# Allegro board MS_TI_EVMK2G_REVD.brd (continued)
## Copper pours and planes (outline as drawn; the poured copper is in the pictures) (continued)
VCC3V3_CP2105 on TOP: 15.57,60.06 15.57,56.23 15.63,56.16 15.63,54.74 16.76,53.61 21.34,53.61 21.46,53.74 21.46,56.02 21.21,56.28 20.07,56.28 19.69,55.89 19.69,55.26 19.43,55.01 17.91,55.01 17.78,55.13 17.78,58.05 18.29,58.56 18.29,60.34 18.16,60.47 16.59,60.47 16.28,60.16 15.67,60.16
VCC3V3_DC_CONN on TOP: 26.04,186.15 26.04,185 26.72,184.32 36.45,184.32 37.24,185.1 37.24,188.08 36.65,188.66 33.58,188.66 31.39,186.48 26.37,186.48
VCC3V3_DC_CONN on TOP: 239.9,238.27 239.9,237.89 247.01,237.89 247.43,238.31 247.43,239.63 247.78,239.97 247.78,243.6 247.27,244.11 243.59,244.11 243.2,243.73 243.2,241.31 242.95,241.06 240.16,241.06 240.03,240.93 240.03,238.39
VCC3V3_DC_CONN on TOP: 200.25,232.91 200.56,232.6 200.56,231.87 200.91,231.51 202.23,231.51 202.39,231.66 202.39,234.36 202.08,234.66 201.63,234.66 201.5,234.79 201.5,235.78 201.17,236.11 199.52,236.11 199.26,235.85 199.26,233.19 199.54,232.91
VCC3V3_DC_CONN on TOP: 26.67,150.51 26.67,148.6 27.31,147.97 30.48,147.97 31.12,148.6 31.12,149.24 31.75,149.87 33.66,149.87 34.29,150.51 34.29,151.14 33.66,151.78 31.12,151.78 29.85,150.51
VCC3V3_DC_CONN on TOP: 224.16,220.87 224.41,220.61 233.3,220.61 234.06,221.38 234.06,230.77 233.43,231.41 229.97,231.41 229.59,231.79 229.59,235.85 229.62,235.88 229.62,237.5 230.38,238.27 233.81,238.27 234.06,238.52 234.06,239.79 233.55,240.3 224.66,240.3 224.16,239.79
VCC3V3_DC_CONN on TOP: 200.28,227.14 200.28,226.02 200.69,225.62 203.86,225.62 204.37,226.13 204.37,227.17 204.17,227.37 200.51,227.37
VCC3V3_DC_CONN on BOTTOM: 225.68,220.82 226.67,219.83 235.2,219.83 236.14,220.77 236.14,225.08 234.52,226.71 230.68,226.71 229.84,227.55 229.84,228.84 229.87,228.87 229.87,237.89 229.36,238.39 226.19,238.39 225.68,237.89
VCC3V3_DC_CONN on L05_PWR1: 4.7,147.08 2.01,149.77 2.01,236.13 14.1,248.22 14.1,249.95 14.5,250.36 230.28,250.36 249.35,250.43 249.94,249.95 249.94,231.03 249.3,230.39 238.38,230.39 236.98,229 236.98,223.92 234.7,221.63 201.14,221.63 199.26,223.51 199.26,231.92 198.75,231.92 198.12,232.55 198.12,233.06 198.25,233.19 198.32,233.19 197.17,234.34 100.7,234.34 95.22,228.87 38.1,228.87 34.29,225.06 34.21,225.06 32.38,223.23 32.36,223.23 32.36,192.12 35.94,188.53 35.94,149.87 33.15,147.08 ; 1 cut-out
VCC3V3_DCIN on TOP: 106.05,187.21 106.05,181.75 105.16,180.86 105.16,179.47 105.28,179.34 108.71,179.34 109.09,179.72 109.09,187.09 108.59,187.59 106.43,187.59
VCC3V3_DCIN on TOP: 107.59,25.01 107.59,23.59 107.16,23.15 105.28,23.15 105.03,23.41 105.03,24.88 105.28,25.14 107.47,25.14
VCC3V3_DCIN on TOP: 231.01,174 243.38,174 243.89,173.5 244.6,173.5 244.73,173.62 244.73,173.88 244.6,174 243.89,174 243.38,174.51 243.2,174.64 240.79,174.64 239.9,175.53 231.01,175.53
VCC3V3_DCIN on TOP: 286.66,199.81 288.98,199.81 290.75,201.59 290.75,202.86 286.69,202.86 286.66,202.83
VCC3V3_DCIN on TOP: 244.09,173.37 244.09,172.99 240.66,172.99 239.39,171.72 230.89,171.72 230.89,173.37
VCC3V3_DCIN on TOP: 278.1,183.73 278.1,192.09 277.11,193.08 277.11,201.64 271.53,201.64 271.53,183.73
VCC3V3_DCIN on TOP: 146.18,105.81 146.18,103.39 145.8,103.01 145.8,98.95 146.05,98.69 148.08,98.69 148.21,98.82 148.21,101.23 148.72,101.74 149.86,101.74 150.24,101.36 150.24,99.2 149.99,98.95 149.99,96.03 150.11,95.9 152.27,95.9 152.4,96.03 152.4,104.41 150.88,105.93 146.3,105.93
VCC3V3_DCIN on TOP: 114.55,194.58 114.94,194.2 118.36,194.2 118.49,194.32 118.49,197.63 117.98,198.13 117.98,200.67 117.86,200.8 116.08,200.8 115.95,200.67 115.95,198.01 116.33,197.63 116.33,196.61 116.08,196.36 114.68,196.36 114.55,196.23
VCC3V3_DCIN on TOP: 86.08,178.73 86.08,176.88 86.13,176.82 94.67,176.82 95.53,175.96 95.53,171.69 95.76,171.46 98.78,171.46 99.36,172.05 99.36,177.31 97.92,178.75 94.82,178.75 94.77,178.7 86.11,178.7
VCC3V3_DCIN on TOP: 274.07,160.42 274.07,152.92 274.7,152.29 286.26,152.29 287.27,153.3 287.27,161.3 286.26,162.32 275.97,162.32
VCC3V3_DCIN on TOP: 148.97,47.94 148.97,46.19 149.33,45.84 153.62,45.84 153.95,46.17 153.95,47.36 153.26,48.05 149.12,48.05 149.02,47.94
VCC3V3_DCIN on BOTTOM: 250.16,176.62 250.16,174.18 252.78,174.18 252.78,176.62
VCC3V3_DCIN on BOTTOM: 274.19,158.51 274.19,153.81 273.81,153.43 273.81,150.76 274.07,150.51 274.07,148.99 274.45,148.6 276.48,148.6 276.86,148.99 276.86,151.78 277.11,152.03 280.92,152.03 281.31,152.41 281.31,158.76 281.05,159.02 274.7,159.02
VCC3V3_DCIN on BOTTOM: 230.76,177.18 230.76,170.07 231.52,169.31 243.97,169.31 244.22,169.56 244.22,170.32 243.71,170.83 242.19,170.83 241.43,171.59 241.43,175.15 238.38,178.2 231.77,178.2
VCC3V3_DCIN on BOTTOM: 115.47,200.04 115.47,191.68 118.31,188.84 118.31,183.99 116.15,181.83 116.15,178.58 116.76,177.97 119.56,177.97 120.22,178.63 120.22,190.59 118.34,192.47 118.29,192.47 118.29,194.22 119.05,194.99 119.05,197.32 118.06,198.31 118.06,199.51 117.45,200.12 115.54,200.12
VCC3V3_DCIN on BOTTOM: 149.15,47.51 149.15,45.94 149.56,45.53 153.97,45.53 154.43,45.99 154.43,47.46 154.08,47.82 151.51,47.82 151.28,47.59 149.22,47.59
VCC3V3_DCIN on L03_SIG1: 164.08,142 164.08,140.98 163.7,140.6 161.16,140.6 160.74,141.02 160.74,141.76 160.66,141.85 160.66,142.81 160.05,143.42 160.05,146.98 161.67,148.6 164.59,148.6 164.72,148.48 164.72,147.33 165.1,146.95 165.35,146.95 165.61,147.21 165.61,148.1 166.24,148.73 169.04,148.73 170.18,147.59 170.18,146.7 169.93,146.45 169.16,146.45 169.04,146.57 169.04,147.08 168.15,147.97 166.62,147.97 166.37,147.72 166.37,147.33 166.75,146.95 166.88,146.95 167.51,146.32 167.51,144.67 166.75,143.91 162.18,143.91 161.8,143.52 161.8,142.51 162.05,142.25 163.83,142.25
VCC3V3_DCIN on L03_SIG1: 105.66,23.61 105.66,24.68 107.06,24.68 107.06,23.61
VCC3V3_DCIN on L05_PWR1: outline of 88 points within 4.83,8.14 291.46,233.19
VCC3V3_DCIN on L06_PWR2: outline of 120 points within 118.11,8.27 298.45,206.64 ; 1 cut-out
VCC3V3_HDMI on TOP: 113.54,31.76 113.54,25.92 112.78,25.16 108.48,25.16 108.23,25.41 106.38,25.41 106.17,25.62 106.17,28.39 106.38,28.59 108.41,28.59 108.84,29.02 108.84,31.76
VCC3V3_MLB on L06_PWR2: 119.08,22.01 119.08,16.02 118.11,15.05 118.11,8.9 118.75,8.27 131.95,8.27 132.41,8.73 132.41,35.07 131.22,36.26 127.28,36.26 126.75,35.73 126.75,29.63 119.13,22.01
VCC3V3_NAND on TOP: 116.71,131.71 116.71,127.78 116.97,127.52 121.79,127.52 122.17,127.9 122.17,131.21 121.54,131.84 116.84,131.84
VCC3V3_NAND on TOP: 114.81,111.77 114.81,109.49 115.19,109.11 117.86,109.11 118.11,108.85 118.11,107.2 117.98,107.08 117.98,105.81 118.75,105.04 123.95,105.04 124.33,105.42 124.46,105.42 124.46,111.01 123.06,112.41 115.44,112.41
VCC3V3_PCIE on TOP: 202.77,234.66 202.77,232.7 202.9,232.58 203.91,232.58 204.04,232.7 206.78,232.7 206.91,232.58 210.19,232.58 210.26,232.65 210.26,233.34 210.13,233.47 207.75,233.47 207.34,233.87 204.39,233.87 203.78,234.48 203.78,237.05 203.25,237.58 202.29,237.58 201.88,237.17 201.88,235.09 202.08,234.89 202.54,234.89
VCC3V3_PCIE on TOP: 214.88,232.42 214.88,230.52 217.42,230.52 217.68,230.27 217.68,226.33 217.93,226.07 223.01,226.07 223.65,226.71 223.65,239.41 223.27,239.79 221.36,239.79 221.11,239.54 221.11,234.96 220.98,234.84 218.82,234.84 218.19,234.2 218.19,232.81 217.8,232.42
VCC3V3_PCIE on BOTTOM: 202.18,226.84 202.82,226.2 224.16,226.2 224.66,226.71 224.66,238.14 224.61,238.19 224.69,238.27 224.69,244.49 225.2,245 228.22,245 228.47,245.25 228.47,250.13 228.32,250.28 206.2,250.28 206.17,250.31 202.54,250.31 202.18,249.95
VCC3V3_PCIE on L03_SIG1: 217.55,231.28 217.55,226.33 218.06,225.82 223.52,225.82 224.66,226.96 224.66,236.11 225.42,236.87 230.25,236.87 230.89,237.5 230.89,248.43 230.12,249.19 225.3,249.19 224.54,248.43 224.54,245.38 226.06,243.85 226.06,240.68 225.55,240.17 221.61,240.17 221.23,239.79 221.23,234.96
VCC3V3_PCIE_AUX on TOP: 200.81,228.08 201.02,227.88 203.07,227.88 203.33,228.13 206.22,228.13 207.47,229.38 207.47,230.19 207.85,230.57 210.13,230.57 210.31,230.75 210.31,231.28 210.16,231.43 207.44,231.43 207.21,231.21 206.12,231.21 205.92,231 205.92,229.81 205.82,229.71 203.71,229.71 203.56,229.86 203.56,230.75 203.23,231.08 200.99,231.08 200.81,230.9
VCC3V3_QSPI on BOTTOM: 188.09,79.14 188.09,76.98 188.59,76.47 192.15,76.47 193.04,75.58 193.04,73.8 193.29,73.55 194.69,73.55 195.71,72.53 195.71,69.23 196.72,68.21 202.69,68.21 203.58,69.1 203.58,69.86 203.07,70.37 202.56,70.37 202.44,70.5 202.44,73.17 203.33,74.06 204.85,74.06 205.36,74.56 205.36,77.61 204.72,78.25 202.82,78.25 202.69,78.12 202.69,76.34 201.8,75.45 197.1,75.45 196.34,76.21 196.34,81.04 196.22,81.17 194.56,81.17 194.31,80.91 194.31,79.77 194.06,79.52 188.47,79.52
VCC3V3_SER_EXP on TOP: 294.54,243.75 294.54,239.26 294.69,239.11 296.21,239.11 296.6,239.49 301.04,239.49 301.62,238.9 301.62,233.69 302.06,233.26 304.06,233.26 304.47,233.67 304.47,241.31 304.09,241.7 297.89,241.7 297.31,242.28 297.31,243.09 296.32,244.08 294.87,244.08
VCC3V3_XDS on TOP: 226.82,50.81 222.88,50.81 222.25,50.18 222.25,39.77 222.88,39.13 226.31,39.13 226.82,39.64
VCC3V3_XDS on L06_PWR2: 225.81,103.65 245.24,103.65 248.41,106.82 297.18,106.82 297.81,106.19 297.81,13.22 293.75,9.16 188.47,9.16 187.71,9.92 187.71,68.72 188.98,69.99 188.98,76.72 191.64,79.39 234.82,79.39 239.65,84.22 239.65,96.15 235.97,99.84 227.2,99.84 225.81,101.23
VCC3V3_XDS_DVDD33 on TOP: 227.2,41.16 227.2,38.62 227.33,38.5 229.36,38.5 229.62,38.75 229.62,40.91 229.23,41.29 227.33,41.29
VCC3V3_XDS_DVDD33 on L06_PWR2: 227.46,59.07 247.4,59.07 247.4,50.43 247.78,50.05 253.87,50.05 255.14,48.78 255.14,43.45 254.25,42.56 244.47,42.56 242.63,40.72 237.93,40.72 236.73,39.51 230.5,39.51 229.74,38.75 227.46,38.75 227.08,39.13 227.08,58.69
VCC5V0_DCDC on TOP: 246.13,176.16 246,176.29 246,176.54 245.62,176.93 245.62,178.83 245.75,178.96 245.75,179.47 246,179.72 247.27,179.72 247.78,180.23 247.78,181.12 247.27,181.62 247.27,185.31 247.65,185.69 251.97,185.69 252.35,185.31 252.35,181.37 251.71,180.74 251.08,180.74 250.82,180.48 250.82,179.59 250.7,179.47 250.19,179.47 249.3,178.58 247.01,178.58 246.25,177.81 246.25,176.93 246.63,176.54 246.63,176.29 246.51,176.16
VCC5V0_DCDC on TOP: 245.62,205.75 252.22,205.75 252.48,206.01 252.48,214.14 253.75,215.41 253.75,224.55 252.73,225.57 247.14,225.57 245.36,223.79 245.36,206.01
VCC5V0_DCDC on TOP: 283.95,94.86 283.18,95.62 282.17,95.62 282.17,95.11 282.55,94.73 282.55,93.49 283.21,92.83 285.47,92.83 285.47,94.35 284.2,94.35 283.95,94.6
VCC5V0_DCDC on TOP: 242.06,161.05 243.59,161.05 243.84,161.3 243.84,163.72 243.33,164.23 243.33,165.5 243.59,165.75 244.35,165.75 244.6,166 244.6,167.53 244.73,167.65 244.73,169.31 244.6,169.43 244.47,169.43 244.35,169.31 244.35,168.29 243.33,167.27 243.33,166.77 242.82,166.26 242.82,164.61 241.81,163.59 241.81,161.3
VCC5V0_DCDC on TOP: 189.61,232.04 190.12,231.54 192.66,231.54 192.91,231.79 192.91,233.82 192.53,234.2 189.74,234.2 189.61,234.08
VCC5V0_DCDC on TOP: 252.48,160.8 252.48,164.23 251.78,164.92 251.78,169.24 251.46,169.56 249.05,169.56 247.9,170.7 246.89,170.7 246.76,170.58 246.76,170.32 246.89,170.19 247.78,170.19 248.41,169.56 248.41,169.31 248.92,168.8 250.06,168.8 250.57,168.29 250.57,167.02 249.81,166.26 249.81,160.8 250.06,160.54 252.22,160.54
VCC5V0_DCDC on TOP: 285.47,99.18 283.95,99.18 282.42,97.65 282.42,96.89 283.18,96.89 283.69,97.4 285.47,97.4
VCC5V0_DCDC on TOP: 280.14,100.95 279.12,100.95 278.87,100.7 278.87,99.18 279.02,99.02 279.98,99.02 280.14,99.18
VCC5V0_DCDC on BOTTOM: 252.83,172.99 252.83,172.35 257.43,172.35 257.43,173.88 253.72,173.88
VCC5V0_DCDC on BOTTOM: 242.49,163.57 242.49,161.79 243.87,161.79 244.55,161.1 244.55,159.55 246.43,159.55 246.43,163.57
VCC5V0_DCDC on L05_PWR1: outline of 90 points within 179.07,8.4 304.16,249.32 ; 4 cut-outs
VCC5V0_LCD on BOTTOM: 32.13,84.77 32.13,86.63 33.02,87.52 47.27,87.52 48.23,86.55 48.23,68.06 46.2,66.03 32.89,66.03 32.26,66.66 32.26,84.65
VCC5V0_USB0_PM on TOP: 217.27,32.35 219.79,32.35 219.79,34.18 219.48,34.48 217.63,34.48 217.27,34.13
VCC5V0_USB0_PM on TOP: 222.28,52.19 222.28,55.54 217.86,55.54 217.86,52.19
VCC5V0_USB0_PM on BOTTOM: 222.63,55.01 221.87,55.77 220.6,55.77 219.89,55.06 219.89,42.18 217.3,39.59 217.3,32.55 217.93,31.92 221.89,31.92 222.63,32.65
VCC5V0_USB1_PM on TOP: 191.47,22.93 191.47,21.05 191.8,20.72 195.48,20.72 196.06,21.3 196.06,22.72 195.68,23.1 191.64,23.1
VCC5V0_USB1_PM on BOTTOM: 199.24,28.97 199.24,25.16 199.64,24.75 200.36,24.75 200.66,24.45 200.66,23.51 200.41,23.26 191.13,23.26 190.75,22.87 190.75,20.41 191.19,19.98 203.15,19.98 203.83,20.67 203.83,28.84 203.48,29.2 199.47,29.2
VCC5V_VUSB_CP2105 on L08_SIG2: 13.13,62.8 13.13,56.76 13.41,56.48 19.08,56.48 19.56,56.96 19.56,57.72 17.96,59.32 17.96,62.91 17.17,63.69 14.02,63.69
VCC12V0_AUD_EXP on TOP: 293.88,160.92 293.88,158.13 293.75,158 293.75,155.84 293.37,155.46 293.37,152.41 293.5,152.29 294,152.29 294.13,152.16 294.13,149.37 294.77,148.73 297.18,148.73 298.32,147.59 298.32,137.68 298.7,137.3 304.5,137.3 304.56,137.37 304.56,147.58 303.91,148.22 299.59,148.22 297.69,150.13 297.69,160.8 296.8,161.69 294.64,161.69
VCC12V0_AUD_EXP on BOTTOM, L03_SIG1, L08_SIG2: 294.13,157.88 294.13,137.68 294.64,137.17 304.04,137.17 304.55,137.68 304.55,146.19 302.89,147.84 299.97,147.84 297.56,150.26 297.56,158.76 296.67,159.65 294.39,159.65 294,159.27 294,158
VCC12V0_DC_IN on TOP: 133.6,226.58 132.59,226.58 132.59,223.53 132.33,223.28 132.33,217.69 131.57,216.93 131.57,213.12 132.59,212.1 136.65,212.1 137.16,212.61 137.16,219.72 133.6,223.28
VCC12V0_DC_IN on TOP: 291.85,156.22 291.97,156.1 293.24,156.1 293.37,156.22 293.37,161.1 294.11,161.84 294.11,163.18 292.07,163.18 291.85,162.96
VCC12V0_DC_IN on TOP: 239.9,237.58 239.9,235.73 240.16,235.47 240.28,235.47 240.79,234.96 240.79,226.2 240.92,226.07 243.33,226.07 243.46,226.2 243.46,237.53 243.41,237.58
VCC12V0_DC_IN on TOP: 245.54,188.23 239.27,188.23 238.76,187.72 230.5,187.72 230.25,187.97 230.25,190.01 230.38,190.13 242.32,190.13 242.7,189.75 245.41,189.75 245.72,189.45 245.72,188.41
VCC12V0_DC_IN on TOP: 249.94,250.08 249.94,246.65 250.32,246.27 252.48,246.27 253.11,246.9 257.18,246.9 257.68,247.41 257.68,249.82 257.43,250.08
VCC12V0_DC_IN on TOP: 294.13,233.44 294.13,235.35 291.46,235.35 291.46,233.44
VCC12V0_DC_IN on TOP: 291.39,190.26 291.39,192.5 287.55,192.5 287.55,196.33 286.82,197.07 286.82,199.38 289.94,199.38 289.94,200.29 291.21,201.56 291.21,202.96 290.7,203.47 290.07,203.47 289.69,203.85 289.69,206.01 289.05,206.64 288.67,206.64 288.54,206.77 284.1,206.77 284.1,206.39 283.72,206.01 279.4,206.01 278.64,205.25 267.21,205.25 266.7,205.75 266.7,213.63 264.67,213.63 264.67,215.66 265.43,215.66 265.94,216.17 265.94,220.49 265.87,220.55 276.29,220.55 276.73,220.11 276.73,216.42 277.24,215.91 283.46,215.91 283.46,222.77 288.29,222.77 288.8,222.26 288.8,212.23 291.46,212.23 292.35,211.34 292.35,206.26 293.12,206.26 294.18,205.2 294.18,190.26
VCC12V0_DC_IN on BOTTOM: 287.15,193.44 287.15,191.02 287.78,190.39 292.23,190.39 292.35,190.26 294,190.26 294.77,191.02 294.77,193.31 294.39,193.69 287.4,193.69
VCC12V0_DC_IN on L06_PWR2: 297.18,156.22 289.81,156.22 287.53,158.51 287.53,183.4 286.38,184.55 285.37,184.55 284.48,185.43 284.48,206.39 283.72,207.15 269.88,207.15 264.92,202.2 264.92,186.2 263.27,184.55 228.35,184.55 226.06,186.83 226.06,200.17 224.16,202.07 117.6,202.07 113.67,198.13 113.67,142.89 118.75,137.81 118.75,101.61 117.48,100.34 117.48,64.15 126.37,55.26 126.37,29.86 118.75,22.24 118.75,16.27 117.86,15.38 117.86,14.11 117.73,13.98 117.73,9.79 117.48,9.54 116.2,9.54 115.57,8.9 4.45,8.9 3.17,10.17 3.17,36.21 4.45,37.48 4.45,102.12 7.81,105.49 93.03,105.49 98.3,110.76 98.3,124.73 95.89,127.14 95.89,183.02 104.52,183.02 105.79,184.29 105.79,218.45 113.28,225.95 132.08,225.95 146.81,211.22 177.93,211.22 178.44,211.72 178.44,233.11 178.56,233.11 178.56,246.14 181.36,248.93 248.41,248.93 249.81,250.33 275.46,250.33 276.86,248.93 290.83,248.93 299.08,240.68 299.08,158.13 ; 1 cut-out
VCC12V0_MLB on TOP: 117.35,23.76 117.35,18.81 117.98,18.18 117.98,15.25 117.86,15.13 116.71,15.13 116.2,14.62 116.2,13.35 116.33,13.22 117.73,13.22 117.98,13.48 117.98,14.49 118.11,14.62 120.9,14.62 122.05,13.48 122.05,10.56 122.43,10.17 124.21,10.17 124.59,10.56 124.59,11.57 124.46,11.7 124.46,14.11 123.44,15.13 122.05,15.13 121.41,15.76 121.41,23.51 121.03,23.89 117.48,23.89
VCC12V0_PCIE on TOP: 206.12,240.27 206.12,237.63 210.19,237.63 210.19,240.55 209.58,241.16 209.58,245.66 210.31,246.39 218.57,246.39 219.33,247.16 219.33,249.06 219.07,249.32 205.49,249.32 204.85,248.68 204.85,245.63 205.33,245.15 205.33,240.76 205.64,240.45 205.94,240.45
VCC12V0_PCIE on TOP: 249.55,245.38 249.55,249.95 244.09,249.95 244.09,245.38
VCC12V0_PCIE on TOP: 215.26,239.41 215.26,237.63 218.95,237.63 219.46,238.14 219.46,239.28 219.33,239.41
VCC12V0_PCIE on L08_SIG2: 204.98,236.74 207.01,234.71 218.44,234.71 220.34,236.62 220.34,242.74 222.2,244.59 248.89,244.59 249.22,244.92 249.22,249.37 248.67,249.93 205.33,249.93 204.98,249.57
VCC12V0_SER_EXP on TOP: 294.44,238.06 294.44,233.49 294.69,233.24 300.74,233.24 301.17,233.67 301.17,238.22 300.61,238.77 297.23,238.77 296.75,238.29 294.67,238.29
VCC_VBUS_XDS on TOP: 249.05,20.21 249.05,18.18 252.98,18.18 253.36,18.56 256.92,18.56 256.92,20.21
VDD2_PLL1 on TOP: 146.43,96.66 146.43,94.42 145.8,93.79 145.8,93.11 146.05,92.85 147.07,92.85 147.57,93.36 147.57,93.87 147.95,94.25 149.22,94.25 149.48,94.5 149.48,97.17 149.35,97.3 147.07,97.3
VDD2_PLL1 on BOTTOM: 146.81,96.41 146.81,94.5 147.32,93.99 149.61,93.99 149.86,94.25 149.86,96.79 149.35,97.3 147.7,97.3
VDD2_PLL2 on TOP: 144.14,96.66 144.14,94.63 144.65,94.12 144.65,92.85 144.78,92.72 145.29,92.72 145.41,92.85 145.41,94.25 145.92,94.76 145.92,96.41 145.67,96.66
VDD2_PLL2 on BOTTOM: 143.89,95.39 143.89,94.76 144.27,94.38 145.92,94.38 146.18,94.63 146.18,96.53 146.05,96.66 144.53,96.66 144.27,96.92 144.27,98.44 144.65,98.82 144.65,99.71 144.27,100.09 142.88,100.09 142.62,99.84 142.62,96.66
VDDR_VTT on TOP: 117.48,187.47 119.44,189.44 121.98,189.44 122.81,190.26 122.81,196.36 121.41,197.75 119.25,197.75 118.62,198.39 118.62,200.93 119.38,200.93 120.14,200.17 126.87,200.17 131.44,195.59 145.29,195.59 145.8,195.09 145.8,187.85 145.54,187.59 126.62,187.59 125.86,186.83 125.86,166.64 125.48,166.26 118.87,166.26 117.48,167.65
VDDR_VTT on BOTTOM: 120.9,188.36 122.38,189.83 122.38,196.28 120.9,197.75 119.25,197.75 118.62,198.39 118.62,200.04 118.75,200.17 124.59,200.17 125.35,199.4 125.35,195.72 127.38,193.69 145.34,193.69 154.64,184.39 154.64,174.59 153.29,173.24 148.46,173.24 147.45,174.26 147.45,176.67 148.84,178.07 151,178.07 151.64,178.7 151.64,183.02 151,183.66 149.22,183.66 148.59,183.02 147.07,183.02 146.3,183.78 146.3,186.07 144.65,187.72 126.37,187.72 125.98,187.34 125.98,167.65 125.6,167.27 121.54,167.27 120.9,167.91
VINPUT on TOP: 271.53,229 271.02,229.5 255.14,229.5 254.25,228.61 252.98,228.61 252.86,228.49 252.86,227.34 252.73,227.22 251.59,227.22 251.33,227.47 251.33,230.52 251.59,230.77 253.75,230.77 254.25,231.28 254.25,232.04 254.76,232.55 265.94,232.55 266.7,233.31 266.7,240.43 267.21,240.93 273.81,240.93 274.57,240.17 274.57,236.62 276.22,234.96 289.94,234.96 290.7,234.2 290.7,231.92 291.85,230.77 291.85,224.3 291.08,223.53 272.16,223.53 271.53,224.17
VINPUT on BOTTOM: 274.57,212.99 274.57,204.99 275.08,204.48 277.5,204.48 278.26,203.72 287.4,203.72 288.16,204.48 291.08,204.48 292.61,206.01 292.61,209.95 291.08,211.47 291.08,215.91 291.97,216.8 291.97,231.28 291.21,232.04 284.48,232.04 284.35,231.92 284.35,211.09 283.97,210.71 281.94,210.71 280.67,209.44 276.35,209.44 275.97,209.82 275.97,211.85 276.35,212.23 276.35,212.74 276.1,212.99
(no net) on TOP: 1.65,7.48 1.65,248.68 2.42,249.45 304.62,249.45 304.62,7.84 267.49,7.84 267.49,7.48 ; 277 cut-outs
(no net) on BOTTOM: 304.6,7.48 1.65,7.48 1.65,250.48 304.11,250.48 304.57,250.03 304.57,230.39 304.6,230.37 ; 215 cut-outs
(no net) on L03_SIG1: 1.91,8.27 1.91,249.85 191.9,249.85 192.38,250.33 194.21,250.33 194.69,249.85 304.16,249.85 304.16,8.27 180.97,8.27 180.97,22.37 159.64,22.37 159.64,8.27 ; 418 cut-outs
AUD_AGND on TOP: 272.72,41.21 272.69,41.21 272.69,36.67 278.56,36.67 278.56,37.81 278.64,37.73 283.21,37.73 283.59,37.35 283.59,36.97 283.97,36.59 284.86,36.59 285.12,36.34 285.12,34.81 285.37,34.56 287.27,34.56 288.54,33.29 288.54,30.75 289.69,29.61 291.21,29.61 295.91,24.91 295.91,8.37 267.97,8.37 267.97,25.49 267.69,25.77 267.69,39.21 270.03,41.54 272.72,41.54 ; 6 cut-outs
AUD_AGND on BOTTOM: 267.97,25.49 267.97,7.89 295.91,7.89 295.91,24.91 291.21,29.61 289.69,29.61 288.54,30.75 288.54,33.29 287.27,34.56 285.37,34.56 285.12,34.81 285.12,36.34 284.86,36.59 283.97,36.59 283.59,36.97 283.59,37.35 283.21,37.73 282.6,37.73 282.57,37.71 282.57,29.83 281.86,29.12 275.16,29.12 273.51,30.77 273.51,31.56 273.99,32.04 279.37,32.04 280.06,32.73 280.06,34.03 280.03,34.05 280.03,36.62 280.26,36.84 280.26,37.73 278.64,37.73 278.38,37.99 278.38,38.5 277.24,38.5 277.14,38.39 277.14,37.86 277.37,37.63 278.38,37.63 278.89,37.12 278.89,35.6 279.17,35.32 279.17,34.81 279.02,34.66 277.88,34.66 277.75,34.79 277.75,36.44 277.5,36.69 275.59,36.69 275.49,36.59 275.49,33.92 275.21,33.64 273.56,33.64 273.02,34.18 273.02,38.65 273.66,39.28 276.1,39.28 278,41.19 278,41.29 277.75,41.54 269.9,41.54 267.69,39.21 267.69,25.77
AUD_AGND on L02_GND1, L03_SIG1, L08_SIG2: 267.97,25.49 267.97,8.37 295.91,8.37 295.91,24.91 291.21,29.61 289.69,29.61 288.54,30.75 288.54,33.29 287.27,34.56 285.37,34.56 285.12,34.81 285.12,36.34 284.86,36.59 283.97,36.59 283.59,36.97 283.59,37.35 283.21,37.73 278.64,37.73 278.38,37.99 278.38,40.91 277.75,41.54 269.9,41.54 267.69,39.21 267.69,25.77
AUD_AGND on L04_GND2, L07_GND3, L09_GND4: 267.97,25.49 267.97,8.37 295.91,8.37 295.91,24.91 291.21,29.61 289.69,29.61 288.54,30.75 288.54,33.29 287.27,34.56 285.37,34.56 285.12,34.81 285.12,36.34 284.86,36.59 283.97,36.59 283.59,36.97 283.59,37.35 283.21,37.73 278.64,37.73 278.38,37.99 278.38,40.91 277.75,41.54 270.79,41.54 268.45,39.21 267.69,39.21 267.69,25.77
BKLT_L on TOP: 44.6,77.82 44.6,77 44.63,76.98 45.87,76.98 46.51,76.34 51.82,76.34 52.04,76.57 52.04,78.45 51.66,78.83 46.25,78.83 46.23,78.81 46.23,78.78 45.39,77.94 44.73,77.94
BKLT_SW on TOP: 44.55,74.84 44.55,73.88 45.52,73.88 46.51,72.89 52.27,72.89 52.48,73.09 52.48,74.94 52.17,75.25 46.23,75.25 45.82,74.84
CVDD on TOP: 259.94,151.5 259.94,144.57 260.1,144.41 263.78,144.41 264.29,144.92 264.29,145.94 264.54,146.19 267.33,146.19 267.59,146.45 267.59,150.76 266.83,151.53 259.97,151.53
CVDD on L05_PWR1: 150.5,134.51 151,134 170.94,134 171.7,133.24 171.7,123.97 171.07,123.33 171.07,117.74 169.93,116.6 169.93,102.63 170.56,102 206.12,102 209.55,105.42 209.55,113.04 208.28,114.31 206.38,114.31 205.1,115.58 205.1,134.03 211.84,140.76 243.08,140.76 248.97,146.65 257.05,146.65 259.49,144.21 270.08,144.21 270.54,144.67 270.54,146.67 270.51,146.7 270.51,158.76 269.24,160.03 243.2,160.03 240.66,162.57 240.66,172.1 241.87,173.31 242.89,173.31 245.11,175.53 245.11,180.23 243.59,181.75 214.12,181.75 212.72,180.35 212.72,168.54 210.19,166 151.13,166 150.5,165.37 ; 2 cut-outs
CVDD1 on TOP: 170.94,145.18 170.94,139.97 171.58,139.33 173.35,139.33 173.61,139.59 174.37,139.59 174.62,139.84 174.62,145.18 174.5,145.3 171.07,145.3
CVDD1 on L05_PWR1: 176.81,140.02 175.87,139.08 170.05,139.08 169.65,139.49 169.65,148.3 170.94,149.6 174.35,149.6 184.02,159.27 211.33,159.27 212.09,158.51 212.09,155.46 212.34,155.21 236.55,155.21 237.49,156.15 240.74,156.15 241.3,155.59 241.3,153.02 237.19,148.91 221.87,148.91 219.96,150.81 186.13,150.81 181.91,146.6 181.91,144.87 181.56,144.52 177.72,144.52 176.81,143.6
CVDD1 on L06_PWR2: 173.48,143.91 177.29,143.91 178.05,143.14 178.05,132.35 179.32,131.08 179.32,125.49 177.93,124.09 177.93,123.08 176.78,121.93 176.78,119.14 176.66,119.01 176.02,119.01 175.89,118.89 175.89,118 175.26,117.36 173.35,117.36 173.35,114.7 173.1,114.44 170.56,114.44 170.43,114.57 170.43,122.19 170.56,122.32 172.47,122.32 172.85,122.7 172.85,123.08 173.23,123.46 173.23,124.09 172.97,124.35 172.97,127.65 170.81,129.81 170.81,143.27 171.07,143.52 173.1,143.52 ; 1 cut-out
CVDD1 on L08_SIG2: 238.51,156.05 238.51,155.46 237.11,154.07 237.11,152.67 237.62,152.16 237.64,152.19 238.33,152.19 243.84,146.67 243.97,146.67 244.45,146.19 250.95,146.19 251.46,146.7 251.46,154.07 249.94,155.59 243.97,155.59 243.08,156.48 243.08,156.99 242.82,157.24 239.39,157.24 238.89,156.73 238.89,156.43
DSS_3V3 on L05_PWR1: 122.73,69.15 122.73,57.22 124.03,55.92 129.34,55.92 135.23,50.03 145.29,50.03 146.06,50.8 146.06,53.75 150.72,58.41 163.68,58.41 163.7,58.43 165.48,58.43 166.88,59.83 166.88,70.25 166.62,70.5 162.13,70.5 161.67,70.04 123.55,70.04 122.68,69.18 122.71,69.15
LDO1_1V8 on TOP: 247.52,167.53 247.9,167.53 248.41,167.02 248.41,166 249.43,164.99 249.43,161.18 249.17,160.92 247.65,160.92 247.4,161.18 247.4,163.84 247.9,164.35 247.9,165.37 247.65,165.62 247.14,165.62 246.89,165.88 246.89,167.4 246.25,168.04 246.25,169.31 246.38,169.43 246.63,169.43 246.76,169.31 246.76,168.29
LDO1_1V8 on L03_SIG1: 241.78,147.49 240.87,146.57 240.87,144.01 242.27,142.61 248.95,142.61 250.98,144.64 250.98,156.4 249.81,157.57 247.07,157.57 246.53,157.04 246.53,156.05 246.89,155.69 248.92,155.69 249.43,155.18 249.43,152.59 246.38,149.54 246.38,148.15 245.72,147.49
LDO2_1V8 on TOP: 168.68,227.6 168.68,230.39 166.52,230.39 166.52,227.6
LDO2_1V8 on TOP: 246.63,161.18 244.73,161.18 244.47,161.43 244.47,165.5 244.98,166 244.98,169.31 245.11,169.43 245.24,169.43 245.36,169.31 245.36,168.16 246.13,167.4 246.13,165.75 246,165.62 245.62,165.62 245.36,165.37 245.36,163.59 245.62,163.34 246.51,163.34 246.89,162.96 246.89,161.43
LDO4_1V8 on TOP: 258.57,180.86 258.57,179.34 255.52,179.34 255.27,179.08 255.27,176.93 254.99,176.65 250.47,176.65 250.44,176.67 250.44,177.43 251.31,178.3 253.09,178.3 254.89,180.1 255.78,180.1 256.54,180.86
LDO6_3V3 on BOTTOM: 234.75,160.31 234.75,156.28 235.64,155.39 237.41,155.39 237.85,155.82 237.85,158 237.88,158.04 240.88,158.04 241.4,158.56 241.4,159.32 240.79,159.93 240.79,160.77 240.46,161.1 235.53,161.1
LDO8_3V3 on TOP: 237.49,160.03 237.49,161.69 234.92,161.69 234.92,160.03
LDO8_3V3 on L08_SIG2: 226.85,162.65 226.85,159.32 228.02,158.16 235.48,158.16 235.69,158.36 237.36,158.36 239.22,160.21 239.22,161.43 237.13,163.51 227.66,163.51 226.82,162.68
OSCVSS on TOP, L02_GND1: 247.17,51.35 247.17,50.79 247.33,50.62 249.24,50.62 249.53,50.92 251.46,50.92 251.61,50.76 251.61,49.29 251.79,49.11 255.8,49.11 257.2,50.51 257.2,54.42 255.75,55.87 251.46,55.87 250.95,55.36 250.95,53.51 249.38,51.93 247.75,51.93
PMIC_VDD1 on TOP: 249.81,151.27 250.06,151.53 250.06,155.34 249.81,155.59 244.22,155.59 243.71,156.1 241.68,156.1 241.43,155.84 241.43,152.03 242.19,151.27
PMIC_VDD1 on TOP: 230.76,185.31 230.76,182.01 240.66,182.01 240.92,182.26 240.92,183.28 239.65,184.55 235.84,184.55 234.06,186.32 231.77,186.32
PMIC_VDD1 on BOTTOM: 249.81,151.27 250.06,151.53 250.06,155.34 249.81,155.59 244.22,155.59 243.71,156.1 241.68,156.1 241.43,155.84 241.43,152.29 242.44,151.27 244.22,151.27 244.47,151.02 244.47,149.24 244.73,148.99 245.24,148.99 245.49,149.24 245.49,151.02 245.75,151.27
PMIC_VDD1 on L03_SIG1: 226.12,162.89 224.79,164.23 224.79,185.31 227.06,187.58 243.22,187.58 245.87,184.93 245.87,174.51 245.75,174.39 245.24,174.39 244.86,174.77 241.81,174.77 238.63,177.94 229.36,177.94 228.09,176.67 228.09,173.5 231.65,169.94 231.65,162.32 233.3,160.67 233.3,158 229.62,154.32 229.62,153.18 230.63,152.16 238.38,152.16 239.52,153.3 241.53,153.3 241.53,156.07 241.86,156.4 243.71,156.4 244.65,155.46 247.98,155.46 248.44,155.01 248.44,152.29 247.42,151.27 242.82,151.27 241.43,149.87 226.95,149.87 226.06,150.76 226.06,156.99 226.12,157.05
PMIC_VDD2 on TOP: 227.46,165.75 227.46,162.32 240.41,162.32 240.41,165.75 237.11,165.75 236.73,165.37 230.5,165.37 230.12,165.75
PMIC_VDD2 on BOTTOM: 227.46,165.75 227.46,162.32 240.41,162.32 240.41,165.75 ; 1 cut-out
PMIC_VDD2 on L03_SIG1: 254.89,145.94 254.89,138.32 255.91,137.3 262.76,137.3 263.27,137.81 263.27,144.16 261.24,146.19 255.14,146.19
PMIC_VDD2 on L05_PWR1: 121.16,189.63 121.16,107.58 121.92,106.82 121.92,103.01 121.97,102.96 149.99,102.96 149.99,187.09 146.94,190.13 121.67,190.13
PMIC_VDD2 on L06_PWR2: 225.42,168.29 227.33,166.38 240.03,166.38 241.17,165.24 241.17,162.45 243.2,160.42 252.09,160.42 252.73,161.05 252.73,165.37 253.75,166.38 266.7,166.38 267.33,165.75 267.33,147.97 269.88,145.43 270.51,145.43 271.78,144.16 271.78,140.35 270.64,139.21 259.21,139.21 254.63,134.63 214,134.63 212.09,136.54 212.09,156.96 211.33,157.72 195.55,157.72 192.53,154.7 164.08,154.7 161.54,152.16 153.42,152.16 151.76,150.51 151.76,108.6 148.16,104.99 119.38,104.99 119.38,137.81 114.3,142.89 114.3,197.5 118.11,201.31 223.9,201.31 225.42,199.79
PMIC_VDD_CTRL on TOP: 256.79,156.22 256.79,153.05 257.56,152.29 267.33,152.29 267.59,152.54 267.59,159.27 267.21,159.65 257.68,159.65 256.67,158.64 256.67,156.35
PMIC_VDD_CTRL on TOP: 255.65,186.45 255.91,186.2 262.64,186.2 263.27,186.83 263.27,199.53 262.64,200.17 256.03,200.17 255.65,199.79
PMIC_VDD_CTRL on BOTTOM: 257.05,155.34 257.05,153.3 259.21,151.14 260.22,151.14 260.6,151.53 260.6,151.91 260.86,152.16 267.33,152.16 267.84,152.67 267.84,159.15 267.08,159.91 256.16,159.91 255.52,159.27 255.52,156.86
PMIC_VDD_CTRL on BOTTOM: 255.65,200.04 255.65,186.58 255.91,186.32 263.27,186.32 263.4,186.45 263.4,199.91 263.02,200.29 255.91,200.29
PMIC_VDD_CTRL on L03_SIG1: 257.68,159.65 257.68,156.86 257.18,156.35 257.18,152.29 258.06,151.4 265.56,151.4 267.72,153.56 267.72,153.68 267.84,153.68 268.86,154.7 284.86,154.7 286.38,156.22 286.38,191.78 280.16,198.01 255.65,198.01 253.62,195.98 253.62,191.02 253.68,190.96 253.68,188.17 254.76,187.09 271.27,187.09 272.92,185.43 272.92,169.43 266.7,163.21 266.7,162.57 263.91,159.78 261.62,159.78 261.49,159.91 257.94,159.91
PMIC_VIO on TOP: 267.84,159.91 267.59,160.16 265.81,160.16 263.91,162.07 260.99,162.07 258.06,164.99 255.65,164.99 255.52,165.11 255.52,170.7 257.56,170.7 258.06,170.19 259.21,170.19 259.46,169.94 265.18,169.94 269.37,165.75 273.56,165.75 274.32,164.99 274.32,161.81 272.41,159.91
VCAN0 on TOP: 7.04,196.64 7.04,191.73 8.31,190.46 16.89,190.46 17.37,189.98 17.37,187.49 17.35,187.47 17.35,183.4 18.39,182.36 36.42,182.36 37.59,181.19 37.59,178.32 40.21,178.32 40.21,182.87 38.89,184.19 26.14,184.19 25.32,185 25.32,193.51 24.66,194.17 20.24,194.17 19.79,193.72 19.79,192.45 19.71,192.37 16.99,192.37 16.28,193.08 10.39,193.08 10.06,193.41 10.06,196.81 9.91,196.97 7.09,196.97 7.01,196.89 7.01,196.66
VCAN1 on TOP: 7.21,153.81 7.21,148.07 7.8,147.49 12.09,147.49 13.13,146.45 30.25,146.45 35.23,141.47 40.56,141.47 41.45,142.36 41.45,146.32 38.96,148.81 37.26,148.81 36.83,149.24 36.83,153.08 31.12,158.79 24.66,158.79 24.36,158.49 24.36,150.87 22.86,149.37 11.68,149.37 10.29,150.76 10.29,153.51 9.47,154.32 7.72,154.32
VCOM_BAT on TOP: 189.48,231.28 189.48,228.74 190.5,227.73 193.42,227.73 193.8,228.11 193.8,229.12 193.67,229.25 193.17,229.25 193.04,229.38 193.04,231.15 192.91,231.28
VCOM_BAT on TOP: 197.61,247.66 197.61,245.51 198.25,244.87 199.9,244.87 200.15,245.12 200.15,245.63 200.28,245.76 200.41,245.76 200.53,245.89 200.53,246.39 200.28,246.65 198.75,246.65 198.63,246.78 198.63,247.66 198.5,247.79 197.74,247.79
VCOM_BAT on BOTTOM: 190.12,232.81 190.12,228.23 190.63,227.73 193.67,227.73 193.93,227.98 193.93,229.25 194.18,229.5 194.44,229.5 195.45,230.52 195.45,232.55 197.1,234.2 199.39,234.2 200.66,235.47 200.66,246.65 200.28,247.03 197.99,247.03 197.74,246.78 197.74,240.68 193.17,236.11 193.17,233.31 192.91,233.06 190.37,233.06
VCOM_BAT_FB on TOP: 192.38,250.26 192.18,250.05 192.18,249.8 192.43,249.54 192.66,249.54 192.66,246.9 193.04,246.52 195.45,246.52 196.85,247.92 198.75,247.92 198.88,247.79 198.88,247.16 199.01,247.03 201.04,247.03 201.17,247.16 201.17,249.47 200.76,249.87 196.27,249.87 195.58,249.19 195.58,247.54 195.2,247.16 194.06,247.16 193.8,247.41 193.8,250.26
VCOM_BAT_FB on L03_SIG1: 192.28,250.13 192.28,248.05 192.79,247.54 198.63,247.54 199.14,247.03 200.66,247.03 200.91,247.28 200.91,249.62 196.39,249.62 196.29,249.72 194.13,249.72 193.6,250.26 192.41,250.26
VETH1_AVDDH on TOP: 155.3,48.53 155.3,51.48 150.11,51.48 150.11,48.53
VETH1_AVDDH on BOTTOM: 149.02,51.7 149.02,50.13 150.88,48.27 155.37,48.27 155.63,48.02 155.63,47.64 155.75,47.51 158.42,47.51 158.67,47.77 158.67,49.04 158.04,49.67 156.01,49.67 155.5,50.18 155.5,51.58 154.74,52.34 149.66,52.34
VETH1_AVDDL_PMOS on TOP: 155.83,51.55 155.83,46.22 155.12,45.51 152.88,45.51 152.6,45.23 152.6,37.76 153.24,37.12 165.33,37.12 165.33,42.48 165.02,42.79 160.02,42.79 159.64,43.17 159.64,46.07 158.04,47.67 158.04,51.2 157.56,51.68 155.96,51.68
VETH1_AVDDL_PMOS on BOTTOM: 156.01,51.96 156.01,50.31 156.39,49.93 158.67,49.93 159.05,49.54 159.05,45.23 158.04,44.21 155.75,44.21 155.5,43.96 155.5,42.05 155.63,41.92 159.18,41.92 159.56,41.54 159.56,38.37 159.94,37.99 164.01,37.99 164.77,38.75 164.77,43.58 160.71,47.64 160.71,50.31 158.93,52.08 156.13,52.08
VETH1_AVDDL_PMOS on L03_SIG1: 155.52,51.25 155.52,39.54 155.96,39.11 174.29,39.11 177.55,42.36 177.55,43.25 176.78,44.01 176.28,44.01 174.68,45.61 167.59,45.61 165.39,47.81 162.95,47.81 162.65,48.11 162.65,48.29 160.07,50.87 160.07,50.92 159.66,51.32 155.6,51.32
VHDMI_AVCC12 on TOP: 90.75,41.9 91.64,41.9 91.77,42.03 91.77,46.42 91.36,46.83 90.81,46.83 90.37,46.4 90.37,44.06 90.75,43.68
VUSB_VBUS0 on TOP: 210.79,18.99 211.12,18.66 213.13,18.66 213.59,19.12 213.59,26.43 213.6,26.44 213.6,31.5 214.45,32.35 216.84,32.35 216.84,33.95 216.48,34.3 211.33,34.3 210.69,33.67 210.69,25.77 211.3,25.16 211.3,23.33 210.79,22.82
VUSB_VBUS1 on TOP: 190.65,14.9 190.68,14.87 190.73,14.87 191.34,14.26 191.34,12.69 191.57,12.46 192.56,12.46 192.76,12.26 192.76,10.71 192.86,10.61 193.37,10.61 193.42,10.66 193.42,17.95 194.51,19.04 194.51,20.28 194.44,20.36 190.93,20.36 190.65,20.08
VUSB_VBUS1 on BOTTOM: 190.93,18.48 190.93,15.33 191.26,15 193.42,15 194.01,15.59 203.81,15.59 204.29,16.07 204.29,18.33 203.38,19.24 191.69,19.24
VUSB_VBUS1 on L08_SIG2: 194.94,15.25 203.45,15.25 204.47,16.27 204.47,19.19 203.83,19.83 193.8,19.83 193.79,19.81 191.38,19.81 190.6,19.04 190.6,15.43 190.98,15.05 194.74,15.05
XDS_VBUS on TOP: 255.78,17.92 255.78,13.86 260.48,13.86 260.48,17.92
N17556030 on TOP: 245.75,187.34 245.75,185.43 244.98,184.67 244.98,181.62 245.62,180.99 245.62,180.35 245.49,180.23 244.86,180.23 244.6,180.48 244.6,182.59 244.25,182.59 244.07,182.77 244.07,184.01 244.22,184.16 244.22,185.05 243.97,185.31 243.97,187.34
N17556786 on TOP: 231.77,178.07 237.74,178.07 241.05,174.77 243.33,174.77 243.84,174.26 243.97,174.26 244.09,174.39 244.09,175.15 243.97,175.27 241.81,175.27 236.85,180.23 231.77,180.23
N17556798 on TOP: 237.24,167.27 237.24,168.04 238,168.04 239.09,169.13 239.42,169.13 240.28,169.99 240.28,170.96 241.55,172.23 244.09,172.23 244.09,172.61 241.05,172.61 238,169.56 237.97,169.56 237.76,169.34 237.74,169.34 237.68,169.28 237.67,169.28 237.62,169.23 234.85,169.23 234.77,169.15 231.39,169.15 231.39,167.27 231.52,167.15 237.11,167.15
N17557440 on TOP: 254,165.75 252.22,165.75 251.97,166 251.97,169.43 251.59,169.81 249.17,169.81 248.16,170.83 247.01,170.83 246.89,170.96 246.89,171.34 247.01,171.46 248.54,171.46 249.05,170.96 251,170.96 251.21,170.75 254,170.75
N17628247 on TOP: 280.14,96.76 280.14,98.16 279.76,98.54 275.82,98.54 275.56,98.29 275.56,97.02 275.95,96.64 280.01,96.64
N17734901 on TOP: 134.01,226.56 134.01,223.43 136.3,221.15 140.84,221.15 142.14,222.44 142.14,230.88 141.33,231.69 137.67,231.69 137.11,231.13 135.89,231.13 135.69,230.93 135.69,227.14 135.1,226.56
N17734901 on BOTTOM: 134.01,226.56 134.01,223.43 136.3,221.15 140.84,221.15 142.14,222.44 142.14,230.88 141.33,231.69 137.67,231.69 137.11,231.13 135.59,231.13 135.38,230.93 135.38,230.01 135.69,229.71 135.69,227.14 135.1,226.56
N19209666 on BOTTOM: 182.27,21.43 182.27,16.52 182.65,16.14 185.93,16.14 185.95,16.17 186.21,16.17 187.22,15.15 190.14,15.15 190.47,15.48 190.47,20.77 189.23,22.01 182.85,22.01
N19631412 on TOP: 255.57,213.68 255.57,206.52 256.11,205.98 260.55,205.98 261.04,206.47 261.04,213.04 261.11,213.12 262.1,213.12 262.13,213.15 262.13,213.86 262.1,213.88 255.78,213.88
N19723053 on TOP: 249.96,187.21 252.6,187.21 252.98,187.59 252.98,194.58 252.48,195.09 248.79,195.09 248.03,194.32 248.03,187.47 249.71,187.47
N21235084 on BOTTOM: 208.2,33.8 208.2,25.52 208.51,25.21 213.56,25.21 213.79,25.44 213.79,33.57 213.08,34.28 208.69,34.28
N23623251 on TOP: 238.76,235.35 238.89,235.22 238.89,233.95 239.14,233.69 239.14,229.76 240.16,228.74 240.16,225.19 240.28,225.06 240.28,221.25 239.9,220.87 235.58,220.87 234.95,221.5 234.95,235.09 235.2,235.35
N23623251 on BOTTOM: 234.7,235.17 234.7,230.14 234.95,229.88 234.95,228.61 235.33,228.23 238.76,228.23 239.01,228.49 239.01,229.88 238.89,230.01 238.89,232.3 239.39,232.81 239.42,235.17
N26130196 on TOP: 285.83,197.3 285.83,194.25 287.22,192.85 287.22,183.61 287.17,183.56 279.53,183.56 279.45,183.63 279.45,192.12 282.83,195.49 282.83,197.37 285.75,197.37
N27876508 on TOP, BOTTOM, L03_SIG1, L08_SIG2: 258.76,246.01 264.29,246.01 265.05,245.25 265.05,242.08 266.19,240.93 266.19,233.57 265.56,232.93 258.32,232.93 257.56,233.69 257.56,238.52 258.83,239.79 258.83,242.08 258.76,242.14
N28034077 on TOP, BOTTOM: 271.14,249.7 271.14,243.09 272.29,241.95 275.21,241.95 275.46,241.7 275.46,236.87 276.61,235.73 290.45,235.73 290.83,236.11 290.83,248.81 289.56,250.08 271.53,250.08
N28055806 on TOP, BOTTOM, L03_SIG1, L08_SIG2: 258.06,247.03 267.72,247.03 267.97,246.78 267.97,243.85 268.35,243.47 269.88,243.47 270.38,243.98 270.38,249.32 269.75,249.95 258.44,249.95 258.06,249.57

Small or netless copper shapes (teardrops, artwork), in the pictures only: 2901 on TOP, 1186 on BOTTOM, 1200 on L03_SIG1, 11 on L05_PWR1, 4 on L06_PWR2, 1289 on L08_SIG2

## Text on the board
Ref Des/Assembly Bottom: K2G EVM BOARD-ASSEMBLY BOTTOM REV D
Ref Des/Silkscreen Bottom: A | NAND FLASH
TOP: K2G GENERAL PURPOSE EVM | REV.D
Ref Des/Assembly Top: K2G EVM BOARD-ASSEMBLY TOP REV D
Ref Des/Silkscreen Top: '0' | '1' | DGND | LDO3_1V8 | PMIC_VDD2 | LDO8_3V3 | LDO5_3V3 | LDO6_3V3 | VRTC | LDO7_3V3 | VCC5V0_DCDC | FAULT-LED | 1V8 | LDO1 | VCC3V3_DC_IN | VCC12V0_DC_IN | LDO4_1V8 | VCC1V8_XDS | REV VTG_ DET | LDO2_1V8 | VCC1V2_XDS | VCC3V3_XDS | LCD | UART2 | BMC LCD | SYSCLK SEL | TOUCH | BMC_PORn | BMC | BOOT MODE SEL | LSB | MSB | SEL_LCD | SEL_HDMI | COM8_EN | SPI NOR | EEPROM | MIPI60 SoC JTAG | PCIe | For evaluation only; not FCC approved for resale | CPLD JTAG | PWRON | INA EXPN | AM1802 JTAG | PMIC_HDRST | ON | PMIC_PWRON | UART0_DB9_EN | USB TO SOC UART0 | & BMC UART0 | BMC UART | DCAN0 | DCAN1 | UART0 | BMC LED | RESETSTATz | PLL_LOCK | SoC_LED0 | SoC_LED1 | SoC_LED2 | SoC_LED3 | SoC_LED4 | WARMRSTz | ATTENTIONz | HDMI OUT | BMC_RESETz | BMC JTAG | PWRON_RSTz | VOL- | VOL+ | MLB | COM8 | eMMC | ETHERNET | USB1 | USB0 | uSD CARD | FUSE | XDS200 USB | LINE IN | DC JACK | +12 V | 5 A | LINE OUT | AUDIO EXPANSION | SERIAL EXPANSION | FY160626000104
PAGE_OUTLINE: 23. | SOLDERMASK IS OPEN ON BOTH THE SIDES. | BOARD PACKAGE MUST BE IDENTIFIED AS RoHS COMPLIANT | DETAIL-A
BODY_CENTER: BEZEL OPENING
DEVICE_TYPE_TOP: 7 | 8 | 9 | 10 | 11 | D | F | G | A | H | C | B | E | 1 | 2 | 3 | 4 | 5 | 6 | NEW MOUNTING HOLES | PART NO: | FINISH: | MATERIAL: | PRODUCTION QTY: | WEIGHT: | TITLE : | ASSEMBLY NO: | DRAWING NO: | N7 | DIN ISO 13715 | MISTRAL SOLUTIONS PVT. LTD
User.28: 12 | 13 | 08 | 09 | 10 | 11 | 01 | 07 | 02 | 06 | 05 | 03 | 04 | STRIPLINE | MICROSTRIP | EDGE COUPLED MICROSTRIP | EDGE COUPLED STRIPLINE | TYPE | L1 &L10 | L03 | L08 | LAYER | 5.00 | 4.10 | 4.00 | TRACEWIDTH[MILS] | - | 9.00 | 5.85 | 6.50 | 5.20 | SPACING[MILS] | 50 | 100 | 90 | 55 | 85 | IMPEDANCE[Ohms] | L02&L09 | L04&L02 | L07&L09 | REF LAYER
User.29: INNER-SIGNAL-2 | 11
User.35: FIGURE | SIZE | 8.0 | 10.0 | 28.0 | 30.0 | 32.0 | 36.0 | 40.0 | 42.0 | 44.0 | 50.0 | 52.0 | 66.0 | 70.0 | 90.0 | 120.0 | 126.0 | 34.0 | 62.0 | 128.0 | 140.0 | 76.0x30.0 | 120.0x30.0 | 140.0x40.0 | DRILL CHART: TOP to BOTTOM | ALL UNITS ARE IN MILS | TOLERANCE | +0.0/-0.0 | +2.3622/-2.3622 | PLATED | NON-PLATED | QTY | 1347 | 4062 | 35 | 5 | 1 | 16 | 10 | 100 | 114 | 104 | 4 | 2 | 6 | 12
